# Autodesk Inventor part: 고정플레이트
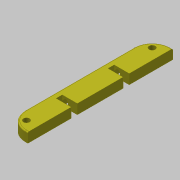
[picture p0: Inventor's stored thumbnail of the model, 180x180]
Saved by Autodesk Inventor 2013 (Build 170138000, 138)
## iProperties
Created: 2018-08
Part Number: 고정플레이트
Material: ABS 플라스틱
Document SubType Name: Modeling
Designer: mduedu
Density: 1.06 g/cm^3
Mass: 13.199 g
Surface Area: 67.9758 cm^2
Volume: 12.4519 cm^3
Author: mduedu
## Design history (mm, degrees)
sketch "스케치1"
  geometry: L1 (0, -60)-(17, -60); L2 (17, -60)-(17, 60); L3 (17, 60)-(0, 60); L4 (0, 60)-(0, -60); 2 further points
  constraints: 8 end point, 2 parallel, 1 coincident, 1 horizontal, 1 midpoint, 1 perpendicular
  dimensions: "d0" = 120 distance between parallel lines of L3 L1; "d2" = 17 distance of L1.start L1.end
extrude "돌출1" new body sketch "스케치1" distance "d3" = 8; taper "d4" = 0 deg
fillet "모깎기1" dims "d5" = 15
fillet "모깎기2" dims "d6" = 1
sketch "스케치2"
  geometry: L1 (-17, 0)-(-17, 7) reference; L2 (0, 0)-(-17, 0) reference; L3 (-12.5, 4)-(-12.5, 0); L4 (-7.5, 4)-(-7.5, 0); A1 r 2.5 centre (-10, 4) between (-12.5, 4) and (-7.5, 4)
  constraints: 4 end point, 2 perpendicular, 2 point on circle, 2 point on line, 2 tangent, 1 centre point
  dimensions: "d7" = 5 diameter of A1; "d8" = 7 distance from line of A1.centre L1; "d9" = 4 distance from line of L2 A1.centre
extrude "돌출2" cut sketch "스케치2" stored distance "d10" = 70; taper "d11" = 0 deg
fillet "모깎기3" dims "d12" = 2.5
sketch "스케치3"
  geometry: L1 (-12.5, -19)-(0, -19); L2 (0, -19)-(0, -24); L3 (0, -24)-(-12.5, -24); L4 (-12.5, -24)-(-12.5, -19); L5 (0, -59)-(0, 59) reference; L6 (-17, 45)-(-17, -45) reference; 2 further points
  constraints: 8 end point, 2 parallel, 1 horizontal, 1 midpoint, 1 perpendicular, 1 vertical alignment
  dimensions: "d13" = 4.5 distance between parallel lines of L4 L6; "d14" = 19 distance from line of L1 point (0, 0); "d15" = 5 distance of L1.end L2.end
extrude "돌출3" cut sketch "스케치3" stored distance "d16" = 70; taper "d17" = 0 deg
sketch "스케치4"
  geometry: A1 r 15 centre (-2, -45) between (-17, -45) and (-2, -60) reference; A2 r 15 centre (-2, 45) between (-2, 60) and (-17, 45) reference; A3 r 10 centre (-2, 45) between (-2, 55) and (-12, 45); A4 r 10 centre (-2, -45) between (-12, -45) and (-2, -55); 3 further points
  constraints: 6 point on circle, 2 centre point, 2 horizontal alignment, 2 vertical alignment
  dimensions: "d18" = 5 radial gap between concentric circles of A3 A2; "d19" = 5 radial gap between concentric circles of A1 A4
hole "구멍1" sketch "스케치4" at (-9.071, 52.071), (-9.071, -52.071) diameter "d20" = 5; stored, may be unused: countersink angle "d24" = 90 deg, drill point angle "d26" = 118 deg; dims "d21" = 6, "d22" = 4, "d23" = 2, "d25" = 8
node "솔리드1"
mirror "대칭1"
